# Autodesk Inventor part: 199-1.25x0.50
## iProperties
Created: 2007-07
Part Number: 199-1.25x0.50
Document SubType Name: Modeling
Designer: btaylor
Density: 1 g/cm^3
Author: btaylor
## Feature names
1. Extrusion1
2. Extrusion2
3. Loft1
4. Extrusion3
5. Extrusion4
6. Extrusion5
7. Fillet1
8. Fillet2
9. Fillet4
10. Extrusion6
11. Extrusion7
12. Extrusion8
13. Chamfer1
14. Chamfer2
15. Chamfer3
16. Fillet5
17. Fillet6
18. Fillet7
19. Extrusion9
20. Fillet10
21. Sweep1
22. Fillet8
23. Fillet9
24. Fillet11
25. Fillet12
